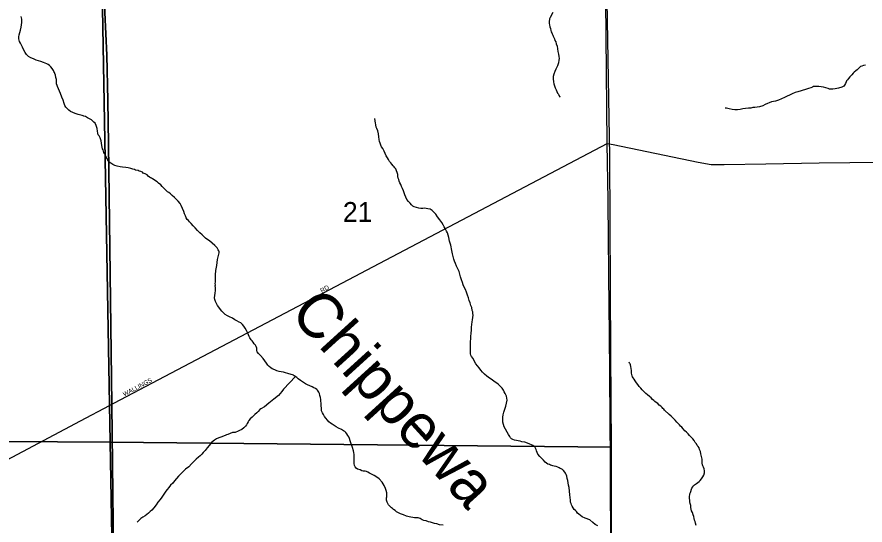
# Model space of a CAD drawing. Extents: x 2010165 to 2382125, y 1060529 to 1407316.
# Drawn here: x 2185920 to 2195389, y 1215496 to 1221171 of the extents above; entities that cross this region are included whole.
import ezdxf

# ---------------------------------------------------------------- set-up
doc = ezdxf.new("R2010")
doc.units = 0
for name, color, linetype in [('GM_X_City_Street', 7, 'Continuous'), ('GM_X_City_Street_Text', 7, 'Continuous'), ('GM_X_Corporation', 7, 'Continuous'), ('GM_X_Minor_River', 7, 'Continuous'), ('GM_X_Minor_River_Text', 7, 'Continuous'), ('GM_X_Section', 7, 'Continuous'), ('GM_X_Section_Text', 7, 'Continuous'), ('GM_X_State_Route', 7, 'Continuous')]:
    doc.layers.add(name, color=color, linetype=linetype)

msp = doc.modelspace()

# ---------------------------------------------------------------- linework, layer by layer
at = {"layer": 'GM_X_City_Street'}
for points in [[(2187007.7, 1216859), (2192510.8, 1219757)], [(2192510.8, 1219757), (2192576.8, 1219745.7), (2193527, 1219550.4), (2193671.5, 1219523.6), (2193814.9, 1219522.4), (2194283, 1219529.6), (2194875.1, 1219541.3), (2196587.7, 1219561), (2201766.1, 1219622.1), (2201818.9, 1219622.6)], [(2178423, 1211913.8), (2179036.1, 1212505.8), (2179410.9, 1212892), (2180199.4, 1213453.7), (2180714.7, 1213808.7), (2181543, 1214385.7), (2181756.8, 1214469.5), (2182287.3, 1214668.4), (2183161.5, 1214990.5), (2183684.1, 1215177.3), (2184009.7, 1215310), (2184380.9, 1215465.7), (2184751.3, 1215661.5), (2186628.9, 1216659.1), (2186954.8, 1216831.2), (2187007.7, 1216859)]]:
    msp.add_lwpolyline(points, dxfattribs=at)
at = {"layer": 'GM_X_Corporation'}
for points in [[(2204447.2, 1221938.7), (2204662.3, 1210529.8), (2204445.3, 1208317.3), (2199872.3, 1208332.6), (2199834.9, 1208326), (2199654.4, 1208314.4), (2199497, 1208304.3), (2197215.9, 1208288.2), (2196205.1, 1208275.6), (2196632.3, 1194905.5), (2192680.8, 1194838.8), (2189318.2, 1194759.1), (2187205, 1194725.9), (2187027.1, 1208132.6), (2187013.9, 1213879), (2186978.3, 1216841.2), (2186941.3, 1219753.4), (2186933.5, 1220238.7), (2186923.4, 1220744.1), (2186878.7, 1221701)], [(2186878.7, 1221701), (2186923.4, 1220744.1), (2186933.5, 1220238.7), (2186941.3, 1219753.4), (2186978.3, 1216841.2), (2187013.9, 1213879), (2187027.1, 1208132.6), (2187205, 1194725.9), (2177123.5, 1194567.9), (2176176.5, 1194580.3), (2174206.9, 1194531), (2167776.4, 1194381.4), (2165054.7, 1194304.8), (2164968.9, 1199659.4), (2164935.2, 1207756.2), (2164931.8, 1207897.8), (2164930.1, 1208081.5), (2164898.5, 1211429), (2164844.7, 1216037.6), (2164832.8, 1218637), (2164895.8, 1221436.7)]]:
    msp.add_lwpolyline(points, dxfattribs=at)
at = {"layer": 'GM_X_Minor_River'}
for points in [[(2186436.7, 1220242.8), (2186421.8, 1220276.5), (2186406.7, 1220314.3), (2186372.5, 1220395.7), (2186368.2, 1220405.6), (2186363.6, 1220425.6), (2186361.1, 1220443.6), (2186360.4, 1220471.7), (2186353.7, 1220495.6), (2186349.1, 1220519.6), (2186344.5, 1220539.5), (2186338.2, 1220551.4), (2186331.9, 1220561.3), (2186327.6, 1220573.2), (2186312.9, 1220596.9), (2186298.4, 1220614.6), (2186284, 1220628.3), (2186269.6, 1220640), (2186253.4, 1220647.6), (2186237.1, 1220655.2), (2186216.9, 1220662.7), (2186188.5, 1220672), (2186160.2, 1220681.3), (2186134, 1220688.6), (2186105.5, 1220701.9), (2186075.1, 1220715.2), (2186048.6, 1220730.5), (2186028, 1220750.1), (2186013.3, 1220773.8), (2185994.4, 1220807.4), (2185981.6, 1220835.2), (2185971, 1220857), (2185960.4, 1220878.8), (2185949.8, 1220898.6), (2185943.4, 1220912.5), (2185941, 1220928.5), (2185942.5, 1220948.6), (2185945.8, 1220972.8), (2185953.2, 1220997.1), (2185960.5, 1221023.4), (2185967.6, 1221057.7), (2185972.9, 1221083.9), (2185976.3, 1221108.1), (2185975.7, 1221128.2), (2185975.2, 1221146.2), (2185972.8, 1221162.2), (2185968.4, 1221176.2)], [(2191902.7, 1221220.2), (2191872.1, 1221163.1), (2191866.5, 1221150.9), (2191864.7, 1221140.8), (2191863.2, 1221124.8), (2191863.5, 1221110.7), (2191863.9, 1221098.7), (2191866.3, 1221082.7), (2191870.9, 1221060.7), (2191875.4, 1221040.7), (2191880.1, 1221018.8), (2191886.4, 1221004.9), (2191892.8, 1220993), (2191897, 1220983.1), (2191901.5, 1220967.1), (2191907.8, 1220957.3), (2191914.2, 1220941.4), (2191920.6, 1220927.5), (2191927.2, 1220907.6), (2191935.6, 1220893.7), (2191942.2, 1220871.8), (2191950.9, 1220843.9), (2191955.7, 1220816), (2191960.5, 1220786), (2191967.3, 1220756), (2191970.1, 1220728), (2191972.6, 1220708), (2191971.2, 1220687.9), (2191965.9, 1220659.6), (2191954.8, 1220625.2), (2191937.8, 1220588.6), (2191926.4, 1220562.2), (2191915.2, 1220533.8), (2191907.9, 1220507.5), (2191906.6, 1220479.3), (2191909.5, 1220447.3), (2191914.1, 1220423.3), (2191920.7, 1220403.4), (2191929.4, 1220379.5), (2191940, 1220355.7), (2191948.5, 1220337.9), (2191957, 1220320), (2191965.4, 1220308.2), (2191971.8, 1220292.3), (2191980.2, 1220280.5), (2191984.3, 1220276.6), (2191986.3, 1220276.6)], [(2195393.5, 1220633.4), (2195371.6, 1220628.8), (2195351.7, 1220622.3), (2195337.8, 1220617.9), (2195322.1, 1220603.4), (2195312.4, 1220593.1), (2195300.7, 1220580.8), (2195287, 1220568.4), (2195269.3, 1220555.9), (2195255.6, 1220543.4), (2195240.1, 1220523), (2195220.7, 1220500.4), (2195203.1, 1220481.8), (2195191.5, 1220467.5), (2195183.7, 1220457.2), (2195180, 1220447.1), (2195172.4, 1220428.8), (2195161, 1220408.4), (2195153.2, 1220398.2), (2195129.5, 1220385.5), (2195091.7, 1220374.5), (2195053.8, 1220367.5), (2195027.8, 1220364.8), (2195009.8, 1220364.3), (2194993.7, 1220365.9), (2194977.5, 1220371.5), (2194951.2, 1220378.8), (2194927, 1220386.2), (2194898.8, 1220389.5), (2194872.6, 1220392.8), (2194852.5, 1220394.3), (2194836.5, 1220395.9), (2194824.4, 1220395.6), (2194814.5, 1220393.3), (2194800.6, 1220386.9), (2194782.7, 1220380.4), (2194758.9, 1220371.8), (2194723.1, 1220360.8), (2194639.5, 1220336.5), (2194607.7, 1220325.6), (2194576.1, 1220310.7), (2194544.4, 1220295.8), (2194518.6, 1220285.1), (2194488.9, 1220272.3), (2194457.3, 1220255.4), (2194421.5, 1220242.4), (2194389.7, 1220231.5), (2194345.9, 1220222.3), (2194320, 1220213.6), (2194298.2, 1220203), (2194274.4, 1220194.4), (2194246.7, 1220179.6), (2194210.9, 1220168.6), (2194183.1, 1220161.8), (2194159, 1220161.2), (2194137, 1220158.6), (2194113.1, 1220154), (2194087.1, 1220151.3), (2194055.1, 1220148.4), (2194025.1, 1220143.6), (2193993.2, 1220136.8), (2193963.3, 1220131.9), (2193935.2, 1220133.2), (2193905, 1220138.4), (2193870.7, 1220145.6), (2193840.5, 1220150.8), (2193826.4, 1220150.4), (2193826.4, 1220150.4)], [(2188038.7, 1218690.7), (2188024.4, 1218700.4), (2188010, 1218714.1), (2187987.3, 1218737.6), (2187962.6, 1218759), (2187935.8, 1218786.4), (2187911, 1218813.9), (2187886.3, 1218839.3), (2187865.5, 1218864.9), (2187847, 1218882.4), (2187834.6, 1218896.2), (2187820.2, 1218909.8), (2187809.7, 1218927.6), (2187801.1, 1218949.5), (2187790.4, 1218973.3), (2187781.7, 1218999.2), (2187753.8, 1219066.7), (2187741.2, 1219086.5), (2187720.5, 1219112), (2187701.9, 1219131.6), (2187679.2, 1219155.1), (2187654.6, 1219176.5), (2187634.1, 1219194.1), (2187617.6, 1219209.7), (2187601.3, 1219219.3), (2187589, 1219229), (2187576.6, 1219242.8), (2187560.1, 1219258.4), (2187541.6, 1219276), (2187525, 1219297.6), (2187502.5, 1219315.1), (2187486, 1219330.7), (2187467.7, 1219342.3), (2187451.4, 1219351.9), (2187435, 1219361.5), (2187422.8, 1219369.2), (2187410.6, 1219374.9), (2187398.4, 1219382.6), (2187384, 1219394.3), (2187373.7, 1219406.1), (2187353.3, 1219419.6), (2187331.1, 1219425), (2187320.7, 1219436.8), (2187302.5, 1219444.4), (2187286.3, 1219447.9), (2187272.1, 1219455.6), (2187243.9, 1219460.9), (2187231.7, 1219466.6), (2187215.5, 1219472.2), (2187191.3, 1219477.6), (2187163, 1219484.9), (2187134.8, 1219490.1), (2187098.6, 1219493.2), (2187072.4, 1219498.5), (2187040.1, 1219505.7), (2187013.9, 1219513.1), (2186991.5, 1219524.5), (2186967.1, 1219537.9), (2186950.8, 1219547.5), (2186940.4, 1219559.3), (2186936, 1219573.2), (2186927.6, 1219589.1), (2186917.1, 1219606.9), (2186906.4, 1219630.7), (2186896, 1219646.5), (2186889.7, 1219656.4), (2186885.3, 1219670.3), (2186882.9, 1219686.3), (2186874.5, 1219698.1), (2186870, 1219718.1), (2186867.5, 1219736.1), (2186864.8, 1219760.1), (2186860.1, 1219786.1), (2186849.2, 1219819.9), (2186836.5, 1219843.7), (2186828.2, 1219855.5), (2186823.7, 1219873.5), (2186821.1, 1219893.5), (2186816.3, 1219925.5), (2186805.4, 1219957.3), (2186792.6, 1219983.1), (2186780.2, 1219996.8), (2186770, 1220004.6), (2186751.5, 1220020.2), (2186731.2, 1220031.7), (2186708.8, 1220045.1), (2186686.3, 1220058.6), (2186668.1, 1220064.1), (2186658.1, 1220065.9), (2186647.9, 1220069.6), (2186631.8, 1220073.2), (2186603.5, 1220080.5), (2186571.1, 1220091.7), (2186542.7, 1220105), (2186518.3, 1220116.4), (2186499.9, 1220130), (2186483.5, 1220145.6), (2186467, 1220163.3), (2186454.4, 1220181), (2186445.8, 1220202.9), (2186436.7, 1220242.8)], [(2190451.8, 1219031.4), (2190429.7, 1219032.8), (2190407.5, 1219036.3), (2190355, 1219051), (2190340.8, 1219058.6), (2190326.4, 1219072.3), (2190309.8, 1219089.9), (2190293.3, 1219109.6), (2190274.6, 1219131.2), (2190261.9, 1219156.9), (2190251.2, 1219182.8), (2190244.6, 1219204.7), (2190235.9, 1219228.5), (2190223.2, 1219256.3), (2190214.6, 1219276.2), (2190206, 1219298), (2190195.4, 1219317.8), (2190188.9, 1219337.7), (2190182.4, 1219353.6), (2190177.9, 1219371.6), (2190173.4, 1219389.5), (2190170.9, 1219409.5), (2190166.2, 1219433.5), (2190159.7, 1219453.4), (2190151.1, 1219475.3), (2190140.8, 1219485), (2190132.4, 1219496.9), (2190122.1, 1219508.6), (2190107.6, 1219526.3), (2190093.1, 1219542), (2190080.7, 1219557.7), (2190070.1, 1219577.6), (2190057.6, 1219597.3), (2190042.9, 1219621), (2190030.2, 1219644.8), (2190019.5, 1219670.6), (2190004.6, 1219700.3), (2189992.1, 1219720.1), (2189983.5, 1219739.9), (2189976.9, 1219761.8), (2189968.4, 1219781.7), (2189963.8, 1219803.6), (2189961, 1219831.7), (2189956.1, 1219865.7), (2189949.2, 1219897.6), (2189938.5, 1219923.4), (2189932, 1219941.3), (2189927.3, 1219967.3), (2189922.7, 1219989.3), (2189918.2, 1220005.2), (2189917.9, 1220017.3), (2189917.6, 1220027.3), (2189917.4, 1220037.3)], [(2191431.2, 1216469.1), (2191422.8, 1216484.9), (2191408.2, 1216506.6), (2191361.7, 1216593.8), (2191351, 1216619.6), (2191344.3, 1216645.5), (2191343.6, 1216669.6), (2191344.8, 1216699.7), (2191348.1, 1216725.9), (2191355.3, 1216758.2), (2191366.4, 1216790.6), (2191377.5, 1216825.1), (2191386.7, 1216855.4), (2191391.8, 1216889.7), (2191391.2, 1216913.8), (2191386.6, 1216933.7), (2191380.2, 1216949.6), (2191371.7, 1216965.5), (2191361.2, 1216985.3), (2191350.7, 1217003.1), (2191336.1, 1217022.8), (2191323.7, 1217038.5), (2191309.1, 1217056.2), (2191294.7, 1217069.9), (2191276.4, 1217081.4), (2191249.8, 1217100.8), (2191227.2, 1217118.3), (2191196.7, 1217137.6), (2191168, 1217158.9), (2191141.3, 1217182.3), (2191116.7, 1217203.7), (2191098, 1217227.3), (2191079.3, 1217250.9), (2191060.7, 1217272.5), (2191044, 1217296.2), (2191029.3, 1217321.9), (2191012.3, 1217355.6), (2190995.7, 1217377.2), (2190989.2, 1217393.1), (2190984.8, 1217409.1), (2190984.2, 1217433.1), (2190983.5, 1217457.2), (2190982.8, 1217483.3), (2190984, 1217513.4), (2190985.1, 1217545.6), (2190986.3, 1217575.7), (2190989.5, 1217605.9), (2190990.8, 1217634.1), (2190993.6, 1217676.3), (2190996.8, 1217706.5), (2190998, 1217736.7), (2191001.3, 1217764.9), (2191004.7, 1217787.1), (2191013.3, 1217839.5), (2191010.8, 1217857.5), (2191008.3, 1217875.5), (2191003.8, 1217893.4), (2190999, 1217925.4), (2190988.3, 1217949.3), (2190979.5, 1217977.1), (2190970.8, 1218003), (2190962, 1218032.9), (2190951.1, 1218064.7), (2190940.2, 1218096.6), (2190927.4, 1218126.3), (2190914.6, 1218152.1), (2190901.9, 1218179.9), (2190893.1, 1218205.8), (2190884.4, 1218233.6), (2190873.4, 1218267.5), (2190866.6, 1218297.4), (2190855.8, 1218327.3), (2190842.9, 1218359.1), (2190828.1, 1218388.8), (2190815.3, 1218416.6), (2190804.5, 1218442.4), (2190797.9, 1218466.3), (2190791.1, 1218496.2), (2190784.2, 1218526.2), (2190775.3, 1218562.1), (2190765.6, 1218622.1), (2190750.3, 1218667.8), (2190741.3, 1218705.8), (2190734.5, 1218733.7), (2190725.8, 1218759.6), (2190717.3, 1218777.4), (2190708.9, 1218793.2), (2190700.4, 1218809.1), (2190691.9, 1218826.9), (2190679.2, 1218850.7), (2190662.5, 1218876.3), (2190641.7, 1218903.9), (2190614.7, 1218939.3), (2190595.9, 1218967), (2190575.2, 1218990.5), (2190554.6, 1219010), (2190532.2, 1219023.5), (2190508, 1219028.9), (2190487.9, 1219032.4), (2190471.8, 1219033.9), (2190451.8, 1219031.4)], [(2189321.1, 1216790.9), (2189318.7, 1216806.9), (2189318.4, 1216817), (2189318, 1216831), (2189317.6, 1216845.1), (2189317.2, 1216861.1), (2189314.8, 1216877.1), (2189312.2, 1216899.1), (2189307.6, 1216921.1), (2189303, 1216943.1), (2189298.4, 1216965), (2189289.9, 1216980.9), (2189283.6, 1216990.8), (2189277.3, 1217000.6), (2189267.1, 1217010.4), (2189252.8, 1217020.1), (2189236.5, 1217029.7), (2189216.1, 1217039.2), (2189191.8, 1217050.6), (2189165.4, 1217061.9), (2189141, 1217073.3), (2189118.6, 1217086.8), (2189085.9, 1217112), (2189061.3, 1217129.5), (2189044.9, 1217143.1), (2189034.7, 1217150.8), (2189016.3, 1217162.4), (2189006.1, 1217170.2), (2188943.4, 1217188.6), (2188919.2, 1217196), (2188894.9, 1217203.4), (2188868.7, 1217206.7), (2188846.5, 1217212.1), (2188822.3, 1217219.5), (2188797.9, 1217230.9), (2188771.5, 1217242.3), (2188753.2, 1217251.8), (2188736.8, 1217265.5), (2188722.3, 1217283.2), (2188705.7, 1217304.8), (2188689, 1217328.5), (2188670.3, 1217354.1), (2188641.2, 1217389.4), (2188616.5, 1217412.9), (2188602, 1217430.6), (2188597.6, 1217444.5), (2188597.3, 1217456.6), (2188596.9, 1217470.6), (2188590.4, 1217488.5), (2188582, 1217504.3), (2188569.5, 1217520.1), (2188559, 1217539.9), (2188544.6, 1217553.5), (2188536.2, 1217565.4), (2188521.7, 1217585.1), (2188513.2, 1217600.9), (2188506.7, 1217620.8), (2188496, 1217644.6), (2188483.3, 1217670.4), (2188468.5, 1217696.1), (2188453.9, 1217717.8), (2188439.3, 1217737.5), (2188418.8, 1217755), (2188400.6, 1217762.6), (2188376.1, 1217776), (2188353.7, 1217789.5), (2188325.2, 1217804.8), (2188294.7, 1217820), (2188270.3, 1217833.4), (2188245.8, 1217848.9), (2188227.3, 1217866.4), (2188206.8, 1217884), (2188160.9, 1217949), (2188148.3, 1217970.8), (2188135.6, 1217994.5), (2188129.1, 1218014.4), (2188126.5, 1218034.4), (2188127.9, 1218058.6), (2188133.1, 1218086.8), (2188136.3, 1218117), (2188135.5, 1218149.1), (2188135, 1218167.2), (2188136.7, 1218179.3), (2188134.2, 1218195.3), (2188135.9, 1218207.4), (2188135.4, 1218227.4), (2188136.7, 1218253.6), (2188137.7, 1218289.8), (2188142.4, 1218340.1), (2188150.9, 1218396.5), (2188159.1, 1218463), (2188169.9, 1218507.4), (2188177.1, 1218537.8), (2188176.9, 1218547.8), (2188172.5, 1218559.7), (2188168.3, 1218569.6), (2188155.6, 1218591.4), (2188130.9, 1218616.8), (2188100.1, 1218644.1), (2188069.3, 1218669.4), (2188038.7, 1218690.7)], [(2193448.2, 1216478.1), (2193429.7, 1216497.6), (2193413.1, 1216515.3), (2193394.6, 1216532.8), (2193378.2, 1216548.5), (2193357.5, 1216570), (2193343, 1216587.7), (2193328.6, 1216601.4), (2193316.2, 1216615.1), (2193303.8, 1216628.8), (2193287.3, 1216646.5), (2193268.7, 1216666.1), (2193246, 1216689.6), (2193223.4, 1216711.1), (2193202.8, 1216730.6), (2193151.4, 1216779.4), (2193143.1, 1216789.3), (2193132.8, 1216799), (2193122.5, 1216808.8), (2193108.1, 1216822.5), (2193091.7, 1216836.1), (2193075.2, 1216851.7), (2193056.8, 1216865.3), (2193042.5, 1216875), (2193030.2, 1216886.7), (2193017.8, 1216898.4), (2192999.3, 1216916), (2192980.8, 1216931.6), (2192960.3, 1216949.1), (2192939.8, 1216966.6), (2192919.2, 1216986.2), (2192900.6, 1217005.8), (2192884, 1217025.4), (2192867.5, 1217045), (2192852.9, 1217064.7), (2192838.3, 1217084.4), (2192823.7, 1217106.1), (2192813.2, 1217125.9), (2192800.8, 1217139.7), (2192792.5, 1217149.5), (2192788.1, 1217161.4), (2192785.8, 1217175.4), (2192783.3, 1217191.4), (2192780.9, 1217205.4), (2192780.4, 1217223.4), (2192777.9, 1217243.5), (2192775.3, 1217265.5), (2192770.8, 1217283.4), (2192766.5, 1217295.4), (2192760.2, 1217305.2), (2192753.9, 1217315.1), (2192755.9, 1217315.2)], [(2189028.8, 1217154.5), (2188898, 1217014.7), (2188878.7, 1216986.1), (2188839.8, 1216942.9), (2188788.7, 1216901.4), (2188731.8, 1216857.8), (2188684.8, 1216816.3), (2188643.2, 1216795.2), (2188631.5, 1216784.8), (2188614, 1216764.3), (2188598.3, 1216749.8), (2188574.8, 1216729.1), (2188547.5, 1216702.3), (2188524, 1216681.6), (2188510.4, 1216663.2), (2188500.8, 1216648.9), (2188491.2, 1216630.5), (2188483.6, 1216616.3), (2188472, 1216599.9), (2188454.5, 1216581.4), (2188430.9, 1216564.7), (2188405.2, 1216550), (2188383.4, 1216541.4), (2188365.5, 1216534.9), (2188355.6, 1216530.6), (2188345.6, 1216530.3), (2188325.6, 1216527.8), (2188301.8, 1216519.1), (2188274, 1216508.4), (2188260, 1216504), (2188246.2, 1216497.6), (2188196.6, 1216478.2), (2188172.7, 1216469.6), (2188147, 1216456.8), (2188127.3, 1216444.3), (2188109.6, 1216431.7), (2188095.8, 1216421.3), (2188080.3, 1216402.9), (2188064.8, 1216382.4), (2188045.4, 1216357.8), (2188022.2, 1216327.1), (2188000.7, 1216306.4), (2187983.1, 1216287.9), (2187965.6, 1216269.3), (2187946, 1216252.8), (2187922.5, 1216232.1), (2187899.1, 1216207.3), (2187869.7, 1216180.5), (2187840.5, 1216147.6), (2187803.2, 1216120.5), (2187777.8, 1216093.7), (2187750.5, 1216066.9), (2187725.1, 1216042.1), (2187701.7, 1216015.4), (2187680.3, 1215990.8), (2187659, 1215964.1), (2187635.6, 1215939.4), (2187614.2, 1215914.7), (2187598.7, 1215894.2), (2187583.2, 1215875.8), (2187565.8, 1215851.2), (2187552.3, 1215830.8), (2187536.9, 1215808.3), (2187517.5, 1215781.7), (2187494.2, 1215752.9), (2187473.1, 1215720.3), (2187449.8, 1215689.5), (2187426.5, 1215662.8), (2187406.9, 1215646.2), (2187389.3, 1215629.7), (2187371.6, 1215615.2), (2187352, 1215598.6), (2187324.3, 1215583.8), (2187304.7, 1215569.3), (2187287.1, 1215552.7), (2187269.5, 1215536.2), (2187262.9, 1215529.3)], [(2190677.5, 1215493.5), (2190639.3, 1215498.5), (2190609, 1215507.8), (2190580.8, 1215513), (2190558.6, 1215518.5), (2190538.3, 1215526), (2190514.1, 1215531.4), (2190489.8, 1215540.8), (2190463.6, 1215546.1), (2190443.3, 1215555.6), (2190420.9, 1215567.1), (2190400.6, 1215574.6), (2190378.5, 1215576), (2190360.5, 1215577.5), (2190298.1, 1215585.9), (2190269.7, 1215595.2), (2190235.3, 1215608.3), (2190200.9, 1215621.5), (2190178.5, 1215632.9), (2190158.1, 1215644.5), (2190141.7, 1215658.1), (2190125.4, 1215669.7), (2190113.1, 1215679.4), (2190100.8, 1215689.1), (2190090.5, 1215698.9), (2190078.2, 1215708.6), (2190069.8, 1215722.4), (2190061.4, 1215736.3), (2190055, 1215752.2), (2190048.6, 1215764.1), (2190046.3, 1215774), (2190046, 1215788.1), (2190047.6, 1215800.2), (2190049.3, 1215812.3), (2190050.8, 1215832.4), (2190050.1, 1215856.4), (2190043.5, 1215880.4), (2190034.8, 1215904.2), (2190019.9, 1215936), (2189998.8, 1215975.6), (2189963.8, 1216010.8), (2189937.2, 1216030.2), (2189908.6, 1216047.5), (2189880.1, 1216062.8), (2189857.8, 1216074.2), (2189839.4, 1216085.8), (2189821.1, 1216095.4), (2189809, 1216097.1), (2189797, 1216098.8), (2189784.9, 1216098.4), (2189770.9, 1216100.1), (2189750.5, 1216111.6), (2189724.2, 1216120.9), (2189705.8, 1216132.5), (2189695.4, 1216146.3), (2189689, 1216162.2), (2189684.4, 1216184.1), (2189683.7, 1216208.2), (2189685.1, 1216230.3), (2189684.4, 1216256.4), (2189683.7, 1216282.5), (2189681.1, 1216304.5), (2189676.6, 1216324.5), (2189667.6, 1216360.4), (2189641.4, 1216438), (2189634.8, 1216461.9), (2189624.3, 1216479.7), (2189613.8, 1216495.5), (2189603.3, 1216515.3), (2189592.9, 1216529.1), (2189580.6, 1216538.8), (2189564.3, 1216546.4), (2189543.8, 1216563.9), (2189509.3, 1216577.1), (2189482.9, 1216592.4), (2189460.4, 1216607.9), (2189438, 1216621.4), (2189419.6, 1216632.9), (2189403.1, 1216648.6), (2189388.6, 1216668.2), (2189370, 1216689.8), (2189353.4, 1216709.5), (2189342.8, 1216729.3), (2189330.2, 1216749), (2189321.6, 1216770.9), (2189321.1, 1216790.9)], [(2192404.2, 1215486.8), (2192377.7, 1215502.1), (2192351, 1215525.5), (2192318.2, 1215552.8), (2192263.5, 1215573.4), (2192231, 1215588.6), (2192210.6, 1215602.2), (2192194.2, 1215615.8), (2192179.8, 1215627.4), (2192167.3, 1215645.2), (2192154.9, 1215658.9), (2192142.6, 1215670.6), (2192132.1, 1215688.4), (2192119.5, 1215708.2), (2192111.1, 1215722), (2192106.7, 1215735.9), (2192102.3, 1215751.9), (2192099.7, 1215773.9), (2192096.9, 1215804), (2192094.1, 1215834), (2192083.8, 1215916.1), (2192079.1, 1215942), (2192074.4, 1215966), (2192069.7, 1215992), (2192065.1, 1216013.9), (2192058.4, 1216041.9), (2192051.8, 1216061.8), (2192045.4, 1216075.7), (2192037.1, 1216085.5), (2192020.6, 1216103.1), (2192010.3, 1216114.9), (2191998, 1216122.6), (2191985.9, 1216128.3), (2191975.7, 1216134.1), (2191959.4, 1216141.7), (2191941.2, 1216149.2), (2191919, 1216152.6), (2191904.9, 1216156.3), (2191890.8, 1216159.9), (2191878.6, 1216163.6), (2191864.4, 1216171.3), (2191848.2, 1216176.9), (2191833.9, 1216186.6), (2191819.5, 1216198.2), (2191800.9, 1216219.8), (2191778.3, 1216241.3), (2191759.6, 1216262.9), (2191736.9, 1216288.4), (2191728.4, 1216306.2), (2191721.9, 1216324.1), (2191715.4, 1216340), (2191709, 1216355.9), (2191702.7, 1216367.8), (2191690.4, 1216375.5), (2191678.2, 1216383.2), (2191664, 1216390.9), (2191645.7, 1216398.4), (2191619.3, 1216409.8), (2191591, 1216421.1), (2191558.7, 1216426.3), (2191538.5, 1216431.8), (2191516.4, 1216435.2), (2191496.2, 1216438.7), (2191476, 1216444.2), (2191457.8, 1216451.7), (2191443.5, 1216459.4), (2191431.2, 1216469.1)], [(2193502.9, 1215491.6), (2193496.3, 1215515.5), (2193491.8, 1215533.5), (2193485.3, 1215549.4), (2193480.8, 1215567.3), (2193476.2, 1215589.3), (2193469.6, 1215611.2), (2193460.9, 1215635.1), (2193452.5, 1215652.9), (2193445.9, 1215672.8), (2193443.4, 1215690.8), (2193442.8, 1215712.9), (2193438.2, 1215734.9), (2193433.7, 1215754.8), (2193431.2, 1215772.8), (2193430.7, 1215790.9), (2193428.3, 1215804.9), (2193429.9, 1215819), (2193431.5, 1215833.1), (2193433.2, 1215845.2), (2193438.9, 1215859.4), (2193455.7, 1215906), (2193465.2, 1215922.3), (2193474.9, 1215936.6), (2193484.7, 1215944.9), (2193494.5, 1215953.2), (2193506.3, 1215961.5), (2193522, 1215972), (2193535.9, 1215980.4), (2193547.5, 1215994.8), (2193563, 1216013.2), (2193576.5, 1216033.7), (2193588, 1216054), (2193595.4, 1216078.3), (2193594.8, 1216100.4), (2193592.1, 1216124.4), (2193583.6, 1216142.3), (2193577.2, 1216156.2), (2193572.9, 1216168.1), (2193572.4, 1216188.2), (2193571.9, 1216204.2), (2193571.2, 1216232.3), (2193564.3, 1216262.2), (2193557.5, 1216292.2), (2193550.8, 1216318.1), (2193542.3, 1216338), (2193535.6, 1216359.9), (2193525.2, 1216373.6), (2193514.9, 1216385.4), (2193506.5, 1216401.3), (2193493.9, 1216419), (2193479.4, 1216438.7), (2193464.8, 1216458.4), (2193448.2, 1216478.1)]]:
    msp.add_lwpolyline(points, dxfattribs=at)
at = {"layer": 'GM_X_Section'}
for points in [[(2188699.1, 1221713.3), (2192497.4, 1221786.2), (2192537.7, 1219610.9), (2192547.4, 1217415.7), (2192553.9, 1216366.5), (2186961.3, 1216421.1), (2186866.2, 1221693.3)], [(2185647.9, 1221682.3), (2186866.2, 1221693.3), (2186961.3, 1216421.1), (2181662, 1216455.1), (2181485, 1221648.7), (2182193.8, 1221655.1)], [(2186961.3, 1216421.1), (2187059.5, 1210937.2), (2181835.9, 1210948.1), (2181662, 1216455.1)], [(2192553.9, 1216366.5), (2192555.1, 1215228.6), (2192573.5, 1213021.2), (2192581.3, 1210907.7), (2187059.5, 1210937.2), (2186961.3, 1216421.1)]]:
    msp.add_lwpolyline(points, close=True, dxfattribs=at)
at = {"layer": 'GM_X_State_Route'}
for points in [[(2192521.6, 1219125.5), (2192510.8, 1219757), (2192492.3, 1221761.1), (2192492.1, 1221780.9)], [(2192535.4, 1217651.9), (2192533.4, 1217922.4), (2192522.1, 1219097.8), (2192521.6, 1219125.5)], [(2192552.9, 1214967.7), (2192551.2, 1215108.4), (2192546.4, 1216193.7), (2192535.4, 1217651.9)]]:
    msp.add_lwpolyline(points, dxfattribs=at)

# ---------------------------------------------------------------- texts
at = {"layer": 'GM_X_City_Street_Text'}
for s, rotation, p in [('RD', 29.36683, (2189324, 1218087.8)), ('WALLINGS', 27.97864, (2187119.8, 1216930.7))]:
    msp.add_text(s, height=50, rotation=rotation, dxfattribs=at).set_placement(p)
at = {"layer": 'GM_X_Minor_River_Text'}
msp.add_text('Chippewa', height=500.24, rotation=312.30847, dxfattribs=at).set_placement((2188952.8, 1217851.7))
at = {"layer": 'GM_X_Section_Text'}
msp.add_text('21', height=221, rotation=0.00001, dxfattribs=at).set_placement((2189559.6, 1218882.4))

doc.saveas('drawing.dxf')
